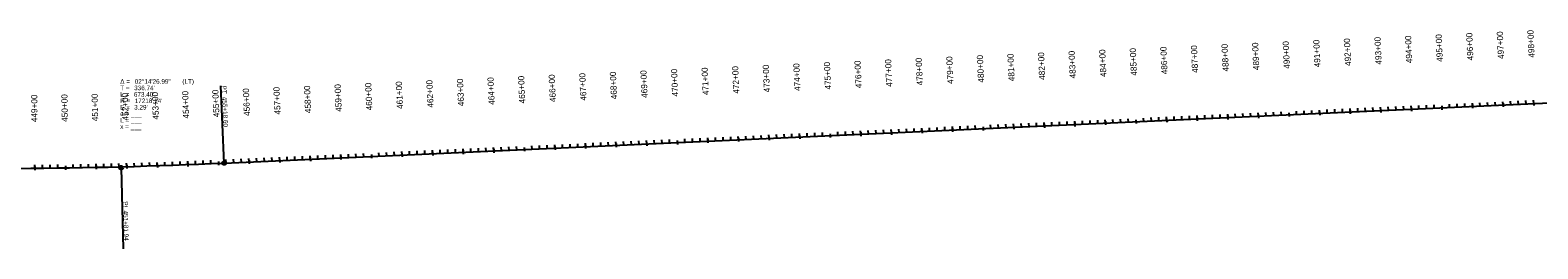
# Model space of a CAD drawing. Extents: x 22693007 to 22771804, y 6223023 to 6251673.
# Drawn here: x 22722562 to 22727487, y 6235531 to 6236243 of the extents above; entities that cross this region are included whole.
import ezdxf

# ---------------------------------------------------------------- set-up
doc = ezdxf.new("R2010")
doc.units = 0
for name, color, linetype in [('Default', 7, 'Continuous'), ('Draft_2', 7, 'Continuous'), ('NamedBoundary', 7, 'Continuous'), ('SheetBorder', 7, 'Continuous'), ('TextAlignment', 7, 'Continuous')]:
    doc.layers.add(name, color=color, linetype=linetype)

msp = doc.modelspace()

# ---------------------------------------------------------------- linework, layer by layer
at = {"layer": 'Default'}
msp.add_line((22723196, 6235810.3), (22730446.9, 6236138.4), dxfattribs=at)
msp.add_arc((22722417.6, 6253010.9), 17218.1, 270.3503, 272.59113, dxfattribs=at)
at = {"layer": 'Draft_2'}
for p, q in [((22727273.3, 6235994.8), (22727272.8, 6236005.7)), ((22727373.2, 6235999.4), (22727372.7, 6236010.3)), ((22727473.1, 6236003.9), (22727472.6, 6236014.8)), ((22726074.5, 6235940.6), (22726074, 6235951.5)), ((22726174.1, 6235951.2), (22726174.7, 6235939)), ((22726274.3, 6235949.6), (22726273.8, 6235960.5)), ((22726374.2, 6235954.1), (22726373.7, 6235965.1)), ((22726474.1, 6235958.7), (22726473.6, 6235969.6)), ((22726574, 6235963.2), (22726573.5, 6235974.1)), ((22726673.6, 6235973.8), (22726674.2, 6235961.6)), ((22726773.8, 6235972.2), (22726773.3, 6235983.1)), ((22726873.7, 6235976.7), (22726873.2, 6235987.7)), ((22726973.6, 6235981.3), (22726973.1, 6235992.2)), ((22727073.5, 6235985.8), (22727073, 6235996.7)), ((22727173.1, 6235996.4), (22727173.6, 6235984.2)), ((22724975.6, 6235890.9), (22724975.1, 6235901.8)), ((22725075.5, 6235895.4), (22725075, 6235906.3)), ((22725175.1, 6235906), (22725175.7, 6235893.8)), ((22725275.3, 6235904.4), (22725274.8, 6235915.3)), ((22725375.2, 6235908.9), (22725374.7, 6235919.8)), ((22725475.1, 6235913.5), (22725474.6, 6235924.4)), ((22725575, 6235918), (22725574.5, 6235928.9)), ((22725674.6, 6235928.6), (22725675.2, 6235916.4)), ((22725774.8, 6235927), (22725774.3, 6235937.9)), ((22725874.7, 6235931.5), (22725874.2, 6235942.4)), ((22725974.6, 6235936.1), (22725974.1, 6235947)), ((22723876.7, 6235841.1), (22723876.2, 6235852)), ((22723976.6, 6235845.6), (22723976.1, 6235856.6)), ((22724076.5, 6235850.2), (22724076, 6235861.1)), ((22724176.2, 6235860.8), (22724176.7, 6235848.6)), ((22724276.3, 6235859.2), (22724275.8, 6235870.1)), ((22724376.2, 6235863.7), (22724375.7, 6235874.6)), ((22724476.1, 6235868.2), (22724475.6, 6235879.2)), ((22724576, 6235872.8), (22724575.5, 6235883.7)), ((22724675.6, 6235883.4), (22724676.2, 6235871.2)), ((22724775.8, 6235881.8), (22724775.3, 6235892.7)), ((22724875.7, 6235886.3), (22724875.2, 6235897.2)), ((22722577.7, 6235793.5), (22722577.6, 6235804.4)), ((22722777.7, 6235796.5), (22722777.4, 6235807.4)), ((22722877.6, 6235798.9), (22722877.4, 6235809.8)), ((22722977.6, 6235801.8), (22722977.3, 6235812.7)), ((22723077.5, 6235805.4), (22723077.1, 6235816.3)), ((22723177.2, 6235815.6), (22723177.7, 6235803.4)), ((22723277.4, 6235814), (22723276.9, 6235824.9)), ((22723377.3, 6235818.5), (22723376.8, 6235829.4)), ((22723477.2, 6235823), (22723476.7, 6235833.9)), ((22723577, 6235827.6), (22723576.6, 6235838.5)), ((22723676.7, 6235838.2), (22723677.2, 6235826)), ((22723776.8, 6235836.6), (22723776.4, 6235847.5)), ((22722677.6, 6235800.8), (22722677.8, 6235788.6))]:
    msp.add_line(p, q, dxfattribs=at)
at = {"layer": 'NamedBoundary'}
msp.add_line((22723196, 6235810.3), (22730446.9, 6236138.4), dxfattribs=at)
msp.add_arc((22722417.6, 6253010.9), 17218.1, 270.3503, 272.59113, dxfattribs=at)
at = {"layer": 'SheetBorder'}
for p, q in [((22727148.4, 6235989.2), (22727147.9, 6236000.1)), ((22727198.3, 6235991.4), (22727197.8, 6236002.3)), ((22727223.3, 6235992.6), (22727222.8, 6236003.5)), ((22727248.3, 6235993.7), (22727247.8, 6236004.6)), ((22727273, 6236000.9), (22727273.5, 6235988.7)), ((22727298.2, 6235996), (22727297.7, 6236006.9)), ((22727323.2, 6235997.1), (22727322.7, 6236008)), ((22727348.2, 6235998.2), (22727347.7, 6236009.1)), ((22727372.9, 6236005.5), (22727373.4, 6235993.2)), ((22727398.1, 6236000.5), (22727397.6, 6236011.4)), ((22727423.1, 6236001.6), (22727422.6, 6236012.5)), ((22727448.1, 6236002.7), (22727447.6, 6236013.6)), ((22727472.8, 6236010), (22727473.3, 6235997.8)), ((22726049.5, 6235939.4), (22726049, 6235950.4)), ((22726099.5, 6235941.7), (22726099, 6235952.6)), ((22726124.4, 6235942.8), (22726123.9, 6235953.7)), ((22726149.4, 6235944), (22726148.9, 6235954.9)), ((22726174.1, 6235951.2), (22726174.7, 6235939)), ((22726199.4, 6235946.2), (22726198.9, 6235957.1)), ((22726224.3, 6235947.4), (22726223.8, 6235958.3)), ((22726249.3, 6235948.5), (22726248.8, 6235959.4)), ((22726274, 6235955.7), (22726274.6, 6235943.5)), ((22726299.3, 6235950.8), (22726298.8, 6235961.7)), ((22726324.2, 6235951.9), (22726323.7, 6235962.8)), ((22726349.2, 6235953), (22726348.7, 6235963.9)), ((22726373.9, 6235960.3), (22726374.5, 6235948)), ((22726399.2, 6235955.3), (22726398.7, 6235966.2)), ((22726424.1, 6235956.4), (22726423.6, 6235967.3)), ((22726449.1, 6235957.5), (22726448.6, 6235968.4)), ((22726473.8, 6235964.8), (22726474.4, 6235952.5)), ((22726499.1, 6235959.8), (22726498.6, 6235970.7)), ((22726524, 6235960.9), (22726523.5, 6235971.8)), ((22726549, 6235962.1), (22726548.5, 6235973)), ((22726573.7, 6235969.3), (22726574.3, 6235957.1)), ((22726599, 6235964.3), (22726598.5, 6235975.2)), ((22726623.9, 6235965.4), (22726623.4, 6235976.4)), ((22726648.9, 6235966.6), (22726648.4, 6235977.5)), ((22726673.6, 6235973.8), (22726674.2, 6235961.6)), ((22726698.9, 6235968.8), (22726698.4, 6235979.7)), ((22726723.8, 6235970), (22726723.3, 6235980.9)), ((22726748.8, 6235971.1), (22726748.3, 6235982)), ((22726773.5, 6235978.3), (22726774.1, 6235966.1)), ((22726798.8, 6235973.4), (22726798.3, 6235984.3)), ((22726823.7, 6235974.5), (22726823.2, 6235985.4)), ((22726848.7, 6235975.6), (22726848.2, 6235986.5)), ((22726873.4, 6235982.9), (22726874, 6235970.6)), ((22726898.6, 6235977.9), (22726898.2, 6235988.8)), ((22726923.6, 6235979), (22726923.1, 6235989.9)), ((22726948.6, 6235980.1), (22726948.1, 6235991)), ((22726973.3, 6235987.4), (22726973.8, 6235975.2)), ((22726998.5, 6235982.4), (22726998.1, 6235993.3)), ((22727023.5, 6235983.5), (22727023, 6235994.4)), ((22727048.5, 6235984.7), (22727048, 6235995.6)), ((22727073.2, 6235991.9), (22727073.7, 6235979.7)), ((22727098.4, 6235986.9), (22727098, 6235997.8)), ((22727123.4, 6235988), (22727122.9, 6235999)), ((22727173.1, 6235996.4), (22727173.6, 6235984.2)), ((22725000.6, 6235892), (22725000.1, 6235902.9)), ((22725025.6, 6235893.1), (22725025.1, 6235904)), ((22725050.5, 6235894.2), (22725050, 6235905.1)), ((22725075.2, 6235901.5), (22725075.8, 6235889.3)), ((22725100.5, 6235896.5), (22725100, 6235907.4)), ((22725125.5, 6235897.6), (22725125, 6235908.5)), ((22725150.4, 6235898.8), (22725149.9, 6235909.7)), ((22725175.1, 6235906), (22725175.7, 6235893.8)), ((22725200.4, 6235901), (22725199.9, 6235911.9)), ((22725225.4, 6235902.2), (22725224.9, 6235913.1)), ((22725250.3, 6235903.3), (22725249.8, 6235914.2)), ((22725275, 6235910.5), (22725275.6, 6235898.3)), ((22725300.3, 6235905.5), (22725299.8, 6235916.5)), ((22725325.3, 6235906.7), (22725324.8, 6235917.6)), ((22725350.2, 6235907.8), (22725349.7, 6235918.7)), ((22725374.9, 6235915), (22725375.5, 6235902.8)), ((22725400.2, 6235910.1), (22725399.7, 6235921)), ((22725425.2, 6235911.2), (22725424.7, 6235922.1)), ((22725450.1, 6235912.3), (22725449.6, 6235923.2)), ((22725474.8, 6235919.6), (22725475.4, 6235907.3)), ((22725500.1, 6235914.6), (22725499.6, 6235925.5)), ((22725525.1, 6235915.7), (22725524.6, 6235926.6)), ((22725550, 6235916.8), (22725549.5, 6235927.8)), ((22725574.7, 6235924.1), (22725575.3, 6235911.9)), ((22725600, 6235919.1), (22725599.5, 6235930)), ((22725625, 6235920.2), (22725624.5, 6235931.1)), ((22725649.9, 6235921.4), (22725649.4, 6235932.3)), ((22725674.6, 6235928.6), (22725675.2, 6235916.4)), ((22725699.9, 6235923.6), (22725699.4, 6235934.5)), ((22725724.9, 6235924.8), (22725724.4, 6235935.7)), ((22725749.8, 6235925.9), (22725749.3, 6235936.8)), ((22725774.5, 6235933.1), (22725775.1, 6235920.9)), ((22725799.8, 6235928.1), (22725799.3, 6235939.1)), ((22725824.7, 6235929.3), (22725824.3, 6235940.2)), ((22725849.7, 6235930.4), (22725849.2, 6235941.3)), ((22725874.4, 6235937.7), (22725875, 6235925.4)), ((22725899.7, 6235932.7), (22725899.2, 6235943.6)), ((22725924.6, 6235933.8), (22725924.2, 6235944.7)), ((22725949.6, 6235934.9), (22725949.1, 6235945.8)), ((22725974.3, 6235942.2), (22725974.9, 6235929.9)), ((22725999.6, 6235937.2), (22725999.1, 6235948.1)), ((22726024.5, 6235938.3), (22726024.1, 6235949.2)), ((22726074.2, 6235946.7), (22726074.8, 6235934.5)), ((22723901.7, 6235842.3), (22723901.2, 6235853.2)), ((22723926.7, 6235843.4), (22723926.2, 6235854.3)), ((22723951.7, 6235844.5), (22723951.2, 6235855.4)), ((22723976.4, 6235851.8), (22723976.9, 6235839.5)), ((22724001.6, 6235846.8), (22724001.1, 6235857.7)), ((22724026.6, 6235847.9), (22724026.1, 6235858.8)), ((22724051.6, 6235849), (22724051.1, 6235859.9)), ((22724076.3, 6235856.3), (22724076.8, 6235844)), ((22724101.5, 6235851.3), (22724101, 6235862.2)), ((22724126.5, 6235852.4), (22724126, 6235863.3)), ((22724151.5, 6235853.6), (22724151, 6235864.5)), ((22724176.2, 6235860.8), (22724176.7, 6235848.6)), ((22724201.4, 6235855.8), (22724200.9, 6235866.7)), ((22724226.4, 6235856.9), (22724225.9, 6235867.9)), ((22724251.4, 6235858.1), (22724250.9, 6235869)), ((22724276.1, 6235865.3), (22724276.6, 6235853.1)), ((22724301.3, 6235860.3), (22724300.8, 6235871.2)), ((22724326.3, 6235861.5), (22724325.8, 6235872.4)), ((22724351.3, 6235862.6), (22724350.8, 6235873.5)), ((22724376, 6235869.8), (22724376.5, 6235857.6)), ((22724401.2, 6235864.9), (22724400.7, 6235875.8)), ((22724426.2, 6235866), (22724425.7, 6235876.9)), ((22724451.2, 6235867.1), (22724450.7, 6235878)), ((22724475.9, 6235874.4), (22724476.4, 6235862.1)), ((22724501.1, 6235869.4), (22724500.6, 6235880.3)), ((22724526.1, 6235870.5), (22724525.6, 6235881.4)), ((22724551.1, 6235871.6), (22724550.6, 6235882.5)), ((22724575.7, 6235878.9), (22724576.3, 6235866.7)), ((22724601, 6235873.9), (22724600.5, 6235884.8)), ((22724626, 6235875), (22724625.5, 6235885.9)), ((22724650.9, 6235876.2), (22724650.5, 6235887.1)), ((22724675.6, 6235883.4), (22724676.2, 6235871.2)), ((22724700.9, 6235878.4), (22724700.4, 6235889.3)), ((22724725.9, 6235879.5), (22724725.4, 6235890.5)), ((22724750.8, 6235880.7), (22724750.4, 6235891.6)), ((22724775.5, 6235887.9), (22724776.1, 6235875.7)), ((22724800.8, 6235882.9), (22724800.3, 6235893.8)), ((22724825.8, 6235884.1), (22724825.3, 6235895)), ((22724850.7, 6235885.2), (22724850.3, 6235896.1)), ((22724875.4, 6235892.4), (22724876, 6235880.2)), ((22724900.7, 6235887.5), (22724900.2, 6235898.4)), ((22724925.7, 6235888.6), (22724925.2, 6235899.5)), ((22724950.6, 6235889.7), (22724950.1, 6235900.6)), ((22724975.3, 6235897), (22724975.9, 6235884.7)), ((22722602.7, 6235793.7), (22722602.6, 6235804.6)), ((22722627.7, 6235794), (22722627.6, 6235804.9)), ((22722652.7, 6235794.3), (22722652.5, 6235805.2)), ((22722702.7, 6235795.1), (22722702.5, 6235806)), ((22722727.7, 6235795.5), (22722727.5, 6235806.4)), ((22722752.7, 6235796), (22722752.5, 6235806.9)), ((22722777.6, 6235802.6), (22722777.8, 6235790.4)), ((22722802.7, 6235797), (22722802.4, 6235807.9)), ((22722827.7, 6235797.6), (22722827.4, 6235808.5)), ((22722852.7, 6235798.2), (22722852.4, 6235809.1)), ((22722877.5, 6235805), (22722877.8, 6235792.7)), ((22722902.6, 6235799.5), (22722902.3, 6235810.5)), ((22722927.6, 6235800.3), (22722927.3, 6235811.2)), ((22722952.6, 6235801), (22722952.3, 6235811.9)), ((22722977.4, 6235807.9), (22722977.8, 6235795.7)), ((22723002.6, 6235802.7), (22723002.2, 6235813.6)), ((22723027.6, 6235803.5), (22723027.2, 6235814.4)), ((22723052.6, 6235804.4), (22723052.2, 6235815.3)), ((22723077.3, 6235811.5), (22723077.8, 6235799.2)), ((22723102.5, 6235806.3), (22723102.1, 6235817.3)), ((22723127.5, 6235807.4), (22723127.1, 6235818.3)), ((22723152.5, 6235808.4), (22723152, 6235819.3)), ((22723177.2, 6235815.6), (22723177.7, 6235803.4)), ((22723202.4, 6235810.6), (22723201.9, 6235821.5)), ((22723227.4, 6235811.7), (22723226.9, 6235822.6)), ((22723252.4, 6235812.9), (22723251.9, 6235823.8)), ((22723277.1, 6235820.1), (22723277.6, 6235807.9)), ((22723302.3, 6235815.1), (22723301.8, 6235826)), ((22723327.3, 6235816.3), (22723326.8, 6235827.2)), ((22723352.3, 6235817.4), (22723351.8, 6235828.3)), ((22723377, 6235824.6), (22723377.5, 6235812.4)), ((22723402.2, 6235819.6), (22723401.7, 6235830.6)), ((22723427.2, 6235820.8), (22723426.7, 6235831.7)), ((22723452.2, 6235821.9), (22723451.7, 6235832.8)), ((22723476.9, 6235829.2), (22723477.4, 6235816.9)), ((22723502.1, 6235824.2), (22723501.6, 6235835.1)), ((22723527.1, 6235825.3), (22723526.6, 6235836.2)), ((22723552.1, 6235826.4), (22723551.6, 6235837.3)), ((22723576.8, 6235833.7), (22723577.3, 6235821.4)), ((22723602, 6235828.7), (22723601.5, 6235839.6)), ((22723627, 6235829.8), (22723626.5, 6235840.7)), ((22723652, 6235830.9), (22723651.5, 6235841.9)), ((22723676.7, 6235838.2), (22723677.2, 6235826)), ((22723701.9, 6235833.2), (22723701.4, 6235844.1)), ((22723726.9, 6235834.3), (22723726.4, 6235845.2)), ((22723751.9, 6235835.5), (22723751.4, 6235846.4)), ((22723776.6, 6235842.7), (22723777.1, 6235830.5)), ((22723801.8, 6235837.7), (22723801.3, 6235848.6)), ((22723826.8, 6235838.9), (22723826.3, 6235849.8)), ((22723851.8, 6235840), (22723851.3, 6235850.9)), ((22723876.5, 6235847.2), (22723877, 6235835)), ((22722577.6, 6235799.6), (22722577.8, 6235787.3)), ((22722677.6, 6235800.8), (22722677.8, 6235788.6))]:
    msp.add_line(p, q, dxfattribs=at)
at = {"layer": 'TextAlignment'}
for p, q in [((22723196, 6235810.3), (22723184.6, 6236062.1)), ((22723184.6, 6236062.1), (22723184.6, 6236062.1)), ((22722859.6, 6235795.1), (22722866.4, 6235531.2)), ((22722866.4, 6235531.2), (22722866.4, 6235531.2))]:
    msp.add_line(p, q, dxfattribs=at)
for centre in [(22723196, 6235810.3), (22722859.6, 6235795.1)]:
    msp.add_circle(centre, 6.24, dxfattribs=at)

# ---------------------------------------------------------------- texts
at = {"layer": 'Draft_2'}
for s, rotation, p in [('490+00', 92.5911, (22726677.1, 6236118)), ('495+00', 92.5911, (22727176.6, 6236140.6)), ('480+00', 92.5911, (22725678.1, 6236072.8)), ('485+00', 92.5911, (22726177.6, 6236095.4)), ('470+00', 92.5911, (22724679.2, 6236027.6)), ('475+00', 92.5911, (22725178.6, 6236050.2)), ('455+00', 92.5293, (22723180.8, 6235959.8)), ('460+00', 92.5911, (22723680.2, 6235982.4)), ('465+00', 92.5911, (22724179.7, 6236005)), ('450+00', 90.8654, (22722685.4, 6235944.8))]:
    msp.add_text(s, height=20.04, rotation=rotation, dxfattribs=at).set_placement(p)
at = {"layer": 'SheetBorder'}
for s, rotation, p in [('488+00', 92.5911, (22726477.3, 6236109)), ('489+00', 92.5911, (22726577.2, 6236113.5)), ('490+00', 92.5911, (22726677.1, 6236118)), ('491+00', 92.5911, (22726777, 6236122.5)), ('492+00', 92.5911, (22726876.9, 6236127)), ('493+00', 92.5911, (22726976.8, 6236131.6)), ('494+00', 92.5911, (22727076.7, 6236136.1)), ('495+00', 92.5911, (22727176.6, 6236140.6)), ('496+00', 92.5911, (22727276.5, 6236145.1)), ('497+00', 92.5911, (22727376.4, 6236149.6)), ('498+00', 92.5911, (22727476.3, 6236154.2)), ('477+00', 92.5911, (22725378.4, 6236059.2)), ('478+00', 92.5911, (22725478.3, 6236063.8)), ('479+00', 92.5911, (22725578.2, 6236068.3)), ('480+00', 92.5911, (22725678.1, 6236072.8)), ('481+00', 92.5911, (22725778, 6236077.3)), ('482+00', 92.5911, (22725877.9, 6236081.8)), ('483+00', 92.5911, (22725977.8, 6236086.4)), ('484+00', 92.5911, (22726077.7, 6236090.9)), ('485+00', 92.5911, (22726177.6, 6236095.4)), ('486+00', 92.5911, (22726277.5, 6236099.9)), ('487+00', 92.5911, (22726377.4, 6236104.4)), ('466+00', 92.5911, (22724279.6, 6236009.5)), ('467+00', 92.5911, (22724379.5, 6236014)), ('468+00', 92.5911, (22724479.4, 6236018.5)), ('469+00', 92.5911, (22724579.3, 6236023.1)), ('470+00', 92.5911, (22724679.2, 6236027.6)), ('471+00', 92.5911, (22724779.1, 6236032.1)), ('472+00', 92.5911, (22724878.9, 6236036.6)), ('473+00', 92.5911, (22724978.8, 6236041.1)), ('474+00', 92.5911, (22725078.7, 6236045.7)), ('475+00', 92.5911, (22725178.6, 6236050.2)), ('476+00', 92.5911, (22725278.5, 6236054.7)), ('455+00', 92.5293, (22723180.8, 6235959.8)), ('456+00', 92.5911, (22723280.6, 6235964.3)), ('457+00', 92.5911, (22723380.5, 6235968.8)), ('458+00', 92.5911, (22723480.4, 6235973.3)), ('459+00', 92.5911, (22723580.3, 6235977.9)), ('460+00', 92.5911, (22723680.2, 6235982.4)), ('461+00', 92.5911, (22723780.1, 6235986.9)), ('462+00', 92.5911, (22723880, 6235991.4)), ('463+00', 92.5911, (22723979.9, 6235995.9)), ('464+00', 92.5911, (22724079.8, 6236000.5)), ('465+00', 92.5911, (22724179.7, 6236005)), ('449+00', 90.5327, (22722586.3, 6235943.5)), ('450+00', 90.8654, (22722685.4, 6235944.8)), ('451+00', 91.1982, (22722784.6, 6235946.7)), ('452+00', 91.531, (22722883.7, 6235949.1)), ('453+00', 91.8637, (22722982.7, 6235952.1)), ('454+00', 92.1965, (22723081.8, 6235955.6))]:
    msp.add_text(s, height=20.04, rotation=rotation, dxfattribs=at).set_placement(p)
at = {"layer": 'TextAlignment'}
for s, p in [('T = ', (22722856.4, 6236047.6)), ('Δ = ', (22722856.4, 6236068.6)), ("336.74'", (22722902, 6236047.6)), ('02°14\'26.99"', (22722903.9, 6236068.6)), (' (LT)', (22723053.6, 6236068.6)), ('L = ', (22722856.4, 6236026.6)), ('R = ', (22722856.4, 6236005.6)), ('E = ', (22722856.4, 6235984.6)), ("673.40'", (22722901.1, 6236026.6)), ("3.29'", (22722902, 6235984.6)), ("17218.14'", (22722903.8, 6236005.6)), ('e = ___ ', (22722856.4, 6235963.6)), ('L = ___', (22722856.4, 6235942.6)), ('x = ___', (22722856.4, 6235921.6))]:
    msp.add_text(s, height=15, dxfattribs=at).set_placement(p)
for s, rotation, p in [('PT', 272.5911, (22723187.9, 6236062.2)), ('455+18.60', 272.5911, (22723189.6, 6236026)), ('PI ', 271.4707, (22722865.7, 6235685.5)), ('451+81.94', 271.4707, (22722866.5, 6235655.6))]:
    msp.add_text(s, height=15, rotation=rotation, dxfattribs=at).set_placement(p)

doc.saveas('drawing.dxf')
